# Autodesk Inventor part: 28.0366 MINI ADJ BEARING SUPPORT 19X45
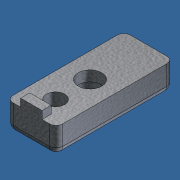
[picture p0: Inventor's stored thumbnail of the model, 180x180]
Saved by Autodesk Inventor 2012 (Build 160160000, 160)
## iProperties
Created: 2015-11
Part Number: 28.0366 MINI ADJ BEARING SUPPORT 19X45
Material: AL 6061-T6
Document SubType Name: Modeling
Designer: Admin
Density: 2.7 g/cm^3
Mass: 18.1484 g
Surface Area: 32.8227 cm^2
Volume: 6.72164 cm^3
Author: Admin
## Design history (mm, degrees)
feature "Base1"
body "Solid1"
